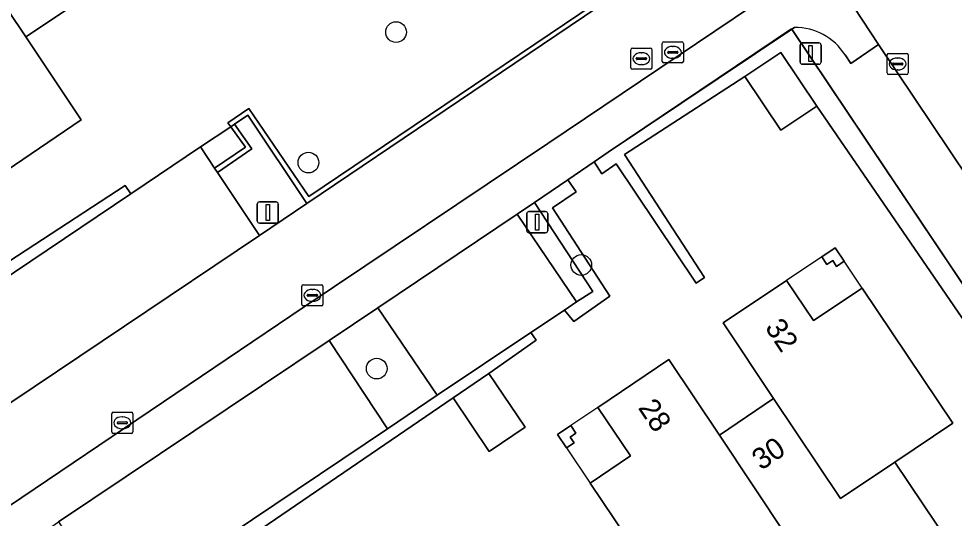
# Model space of a CAD drawing. Extents: x 158793 to 159888, y 384317 to 385256.
# Drawn here: x 159021.67 to 159065.9, y 384757.19 to 384780.77 of the extents above; entities that cross this region are included whole.
import ezdxf

# ---------------------------------------------------------------- set-up
doc = ezdxf.new("R2010")
doc.units = 0
for name, color, linetype in [('IMGEO_Boom', 7, 'Continuous'), ('IMGEO_Erf', 7, 'Continuous'), ('IMGEO_Groenvoorziening', 7, 'Continuous'), ('IMGEO_Haag', 7, 'Continuous'), ('IMGEO_Kolk', 7, 'Continuous'), ('IMGEO_Lichtmast', 7, 'Continuous'), ('IMGEO_Pand', 7, 'Continuous'), ('IMGEO_Pand_nummerreeks', 7, 'Continuous'), ('IMGEO_Pand_overbouw', 7, 'Continuous'), ('IMGEO_Parkeervlak_open', 7, 'Continuous'), ('IMGEO_Rijbaan_lokaal_open', 7, 'Continuous'), ('IMGEO_Rioolput', 7, 'Continuous'), ('IMGEO_Voetpad_open', 7, 'Continuous')]:
    doc.layers.add(name, color=color, linetype=linetype)

msp = doc.modelspace()

# ---------------------------------------------------------------- linework, layer by layer
at = {"layer": 'IMGEO_Boom'}
for centre in [(159039.512, 384780.142), (159035.369, 384773.98), (159048.268, 384769.147), (159038.597, 384764.255)]:
    msp.add_circle(centre, 0.489, dxfattribs=at)
at = {"layer": 'IMGEO_Erf'}
for points in [[(159017.331, 384766.792), (159026.702, 384772.904), (159026.968, 384772.506), (159030.265, 384774.719), (159031.693, 384775.678), (159031.561, 384775.859), (159032.552, 384776.536), (159035.395, 384772.381), (159053.9, 384784.866), (159047.248, 384794.802), (159043.946, 384799.753), (159042.252, 384798.606), (159040.537, 384801.144), (159042.242, 384802.291), (159040.826, 384804.435), (159039.065, 384807.197), (159037.9, 384808.326)], [(159073.463, 384756.185), (159059.406, 384776.641), (159057.7, 384775.506), (159056.001, 384778.049), (159050.315, 384774.368), (159054.088, 384768.56), (159053.696, 384768.284), (159049.917, 384773.924), (159049.246, 384773.456), (159048.88, 384774.02), (159047.625, 384773.167), (159048.029, 384772.609), (159046.909, 384771.846), (159049.623, 384767.68), (159047.913, 384766.485), (159047.469, 384767.022), (159045.889, 384765.966), (159046.137, 384765.595), (159043.901, 384764.02), (159045.607, 384761.491), (159043.913, 384760.348), (159042.209, 384762.873), (159026.999, 384752.507)]]:
    msp.add_lwpolyline(points, dxfattribs=at)
for points in [[(159025.946, 384782.554), (159022.012, 384779.912), (159024.633, 384775.996), (159019.881, 384772.794), (159019.086, 384773.986), (159017.431, 384772.878), (159015.904, 384775.16), (159013.959, 384773.858), (159011.97, 384776.847), (159015.525, 384779.251), (159013.803, 384781.818), (159010.258, 384779.42), (159008.249, 384782.438), (159010.181, 384783.723), (159008.645, 384786.031), (159015.019, 384790.32), (159016.863, 384787.589), (159020.783, 384790.227)], [(159059.638, 384769.531), (159060.27, 384769.954), (159060.694, 384769.323), (159060.336, 384769.083), (159060.152, 384769.357), (159059.877, 384769.173)], [(159052.092, 384752.541), (159052.674, 384752.933), (159048.685, 384758.851), (159050.593, 384760.137), (159049.05, 384762.426), (159052.408, 384764.689), (159054.798, 384761.108), (159057.361, 384762.84), (159054.972, 384766.411), (159057.973, 384768.418), (159059.252, 384766.521), (159061.547, 384768.051), (159065.825, 384761.675), (159063.087, 384759.841), (159065.729, 384755.897), (159058.095, 384750.782), (159058.053, 384750.844), (159054.734, 384748.612)], [(159047.142, 384761.14), (159047.772, 384761.565), (159048.014, 384761.207), (159047.741, 384761.022), (159047.924, 384760.75), (159047.567, 384760.509)]]:
    msp.add_lwpolyline(points, close=True, dxfattribs=at)
at = {"layer": 'IMGEO_Groenvoorziening'}
for points in [[(159037.9, 384808.326), (159039.065, 384807.197), (159040.826, 384804.435), (159042.242, 384802.291), (159043.946, 384799.753), (159047.248, 384794.802), (159053.9, 384784.866), (159035.395, 384772.381), (159032.552, 384776.536), (159031.561, 384775.859), (159031.693, 384775.678), (159031.875, 384775.8), (159032.507, 384776.224), (159035.297, 384772.043), (159052.342, 384783.55)], [(159058.344, 384780.362), (159058.215, 384780.276), (159074.393, 384756.206), (159074.469, 384756.094), (159076.359, 384757.322), (159076.28, 384757.438), (159076.898, 384757.859), (159070.794, 384766.937), (159062.325, 384779.557)], [(159062.325, 384779.557), (159061.017, 384778.659), (159060.74, 384779.07)]]:
    msp.add_lwpolyline(points, dxfattribs=at)
for points in [[(159056.001, 384778.049), (159057.702, 384779.186), (159059.406, 384776.641), (159073.463, 384756.185), (159057.365, 384745.439), (159057.651, 384745), (159058.367, 384745.484), (159074.393, 384756.206), (159058.215, 384780.276), (159049.537, 384774.467), (159048.88, 384774.02), (159049.246, 384773.456), (159049.917, 384773.924), (159053.696, 384768.284), (159054.088, 384768.56), (159050.315, 384774.368)], [(159031.875, 384775.8), (159032.697, 384774.637), (159031.069, 384773.515), (159033.059, 384770.533), (159035.297, 384772.043), (159032.507, 384776.224)], [(159009.089, 384775.491), (159008.609, 384775.168), (159015.56, 384764.829), (159017.507, 384766.155), (159026.968, 384772.506), (159026.702, 384772.904), (159017.331, 384766.792), (159015.636, 384765.657), (159013.986, 384768.23)], [(159046.909, 384771.846), (159048.029, 384772.609), (159047.625, 384773.167), (159046.05, 384772.096), (159048.815, 384767.898), (159048.042, 384767.405), (159047.469, 384767.022), (159047.913, 384766.485), (159049.623, 384767.68)], [(159046.05, 384772.096), (159045.237, 384771.543), (159048.042, 384767.405), (159048.815, 384767.898)], [(159038.657, 384767.131), (159036.344, 384765.586), (159039.107, 384761.407), (159041.461, 384763.006)], [(159042.209, 384762.873), (159043.901, 384764.02), (159046.137, 384765.595), (159045.889, 384765.966), (159041.461, 384763.006), (159039.107, 384761.407), (159026.336, 384752.851), (159024.473, 384751.628), (159030.795, 384742.206), (159031.262, 384742.535), (159027.027, 384748.839), (159025.31, 384751.354), (159026.999, 384752.507)]]:
    msp.add_lwpolyline(points, close=True, dxfattribs=at)
msp.add_arc((159058.37, 384777.542), 2.82, 32.8078, 90.5222, dxfattribs=at)
at = {"layer": 'IMGEO_Haag'}
msp.add_lwpolyline([(159037.9, 384808.326), (159039.065, 384807.197), (159040.826, 384804.435), (159042.242, 384802.291), (159043.946, 384799.753), (159047.248, 384794.802), (159053.9, 384784.866), (159035.395, 384772.381), (159032.552, 384776.536), (159031.561, 384775.859), (159031.693, 384775.678), (159031.875, 384775.8), (159032.507, 384776.224), (159035.297, 384772.043), (159052.342, 384783.55)], dxfattribs=at)
for points in [[(159058.205, 384780.291), (159049.537, 384774.467), (159048.88, 384774.02), (159049.246, 384773.456), (159049.917, 384773.924), (159053.696, 384768.284), (159054.088, 384768.56), (159050.315, 384774.368), (159056.001, 384778.049), (159057.702, 384779.186), (159059.406, 384776.641), (159073.463, 384756.185), (159057.365, 384745.439), (159057.651, 384745), (159058.367, 384745.484), (159074.393, 384756.206)], [(159009.089, 384775.491), (159008.609, 384775.168), (159015.56, 384764.829), (159017.507, 384766.155), (159026.968, 384772.506), (159026.702, 384772.904), (159017.331, 384766.792), (159015.636, 384765.657), (159013.986, 384768.23)], [(159046.909, 384771.846), (159048.029, 384772.609), (159047.625, 384773.167), (159046.05, 384772.096), (159048.815, 384767.898), (159048.042, 384767.405), (159047.469, 384767.022), (159047.913, 384766.485), (159049.623, 384767.68)], [(159026.999, 384752.507), (159042.209, 384762.873), (159043.901, 384764.02), (159046.137, 384765.595), (159045.889, 384765.966), (159041.461, 384763.006), (159039.107, 384761.407), (159026.336, 384752.851), (159024.473, 384751.628), (159030.795, 384742.206), (159031.262, 384742.535), (159027.027, 384748.839), (159025.31, 384751.354)]]:
    msp.add_lwpolyline(points, close=True, dxfattribs=at)
at = {"layer": 'IMGEO_Kolk'}
for p, q in [((159052.095, 384778.76), (159052.095, 384779.612)), ((159052.17, 384779.686), (159053.022, 384779.686)), ((159053.096, 384779.612), (159053.096, 384778.76)), ((159052.354, 384779.18), (159052.354, 384779.192)), ((159052.792, 384779.143), (159052.394, 384779.143)), ((159052.397, 384779.229), (159052.795, 384779.229)), ((159052.583, 384779.466), (159052.608, 384779.466)), ((159052.838, 384779.192), (159052.838, 384779.18)), ((159062.721, 384778.213), (159062.721, 384779.065)), ((159062.796, 384779.139), (159063.648, 384779.139)), ((159063.722, 384779.065), (159063.722, 384778.213)), ((159053.022, 384778.686), (159052.17, 384778.686)), ((159052.606, 384778.906), (159052.581, 384778.906)), ((159062.98, 384778.633), (159062.98, 384778.645)), ((159063.023, 384778.682), (159063.421, 384778.682)), ((159063.209, 384778.919), (159063.234, 384778.919)), ((159063.464, 384778.645), (159063.464, 384778.633)), ((159063.418, 384778.596), (159063.02, 384778.596)), ((159063.232, 384778.359), (159063.207, 384778.359)), ((159063.648, 384778.139), (159062.796, 384778.139)), ((159035.056, 384767.288), (159035.056, 384768.14)), ((159035.131, 384768.214), (159035.983, 384768.214)), ((159036.057, 384768.14), (159036.057, 384767.288)), ((159035.315, 384767.708), (159035.315, 384767.72)), ((159035.753, 384767.671), (159035.355, 384767.671)), ((159035.358, 384767.757), (159035.756, 384767.757)), ((159035.544, 384767.994), (159035.569, 384767.994)), ((159035.799, 384767.72), (159035.799, 384767.708)), ((159035.983, 384767.214), (159035.131, 384767.214)), ((159035.567, 384767.434), (159035.542, 384767.434)), ((159026.071, 384761.27), (159026.071, 384762.122)), ((159026.146, 384762.196), (159026.998, 384762.196)), ((159026.559, 384761.976), (159026.584, 384761.976)), ((159027.072, 384762.122), (159027.072, 384761.27)), ((159026.33, 384761.69), (159026.33, 384761.702)), ((159026.768, 384761.653), (159026.37, 384761.653)), ((159026.373, 384761.739), (159026.771, 384761.739)), ((159026.582, 384761.416), (159026.557, 384761.416)), ((159026.814, 384761.702), (159026.814, 384761.69)), ((159026.998, 384761.196), (159026.146, 384761.196))]:
    msp.add_line(p, q, dxfattribs=at)
for points in [[(159052.095, 384778.76), (159052.095, 384779.612)], [(159052.17, 384779.686), (159053.022, 384779.686)], [(159053.096, 384779.612), (159053.096, 384778.76)], [(159062.721, 384778.213), (159062.721, 384779.065)], [(159062.796, 384779.139), (159063.648, 384779.139)], [(159063.722, 384779.065), (159063.722, 384778.213)], [(159053.022, 384778.686), (159052.17, 384778.686)], [(159063.648, 384778.139), (159062.796, 384778.139)], [(159035.056, 384767.288), (159035.056, 384768.14)], [(159035.131, 384768.214), (159035.983, 384768.214)], [(159036.057, 384768.14), (159036.057, 384767.288)], [(159035.983, 384767.214), (159035.131, 384767.214)], [(159026.071, 384761.27), (159026.071, 384762.122)], [(159026.146, 384762.196), (159026.998, 384762.196)], [(159027.072, 384762.122), (159027.072, 384761.27)], [(159026.998, 384761.196), (159026.146, 384761.196)]]:
    msp.add_lwpolyline(points, dxfattribs=at)
for centre, radius, start, end in [((159052.172, 384779.61), 0.0765, 91.552, 178.448), ((159052.172, 384779.61), 0.0765, 91.552, 178.448), ((159053.02, 384779.61), 0.0765, 1.552, 88.448), ((159053.02, 384779.61), 0.0765, 1.552, 88.448), ((159052.394, 384779.189), 0.0403, 85.8775, 175.7526), ((159052.391, 384779.179), 0.0366, 178.938, 274.7102), ((159052.795, 384779.186), 0.043, 264.8664, 352.4533), ((159052.799, 384779.191), 0.0386, 1.7309, 96.639), ((159062.798, 384779.063), 0.0765, 91.552, 178.448), ((159062.798, 384779.063), 0.0765, 91.552, 178.448), ((159063.646, 384779.063), 0.0765, 1.552, 88.448), ((159063.646, 384779.063), 0.0765, 1.552, 88.448), ((159052.172, 384778.762), 0.0765, 181.552, 268.448), ((159052.172, 384778.762), 0.0765, 181.552, 268.448), ((159053.02, 384778.762), 0.0765, 271.552, 358.448), ((159053.02, 384778.762), 0.0765, 271.552, 358.448), ((159063.02, 384778.642), 0.0403, 85.8775, 175.7526), ((159063.017, 384778.632), 0.0366, 178.938, 274.7102), ((159063.421, 384778.639), 0.043, 264.8664, 352.4533), ((159063.425, 384778.644), 0.0386, 1.7309, 96.639), ((159062.798, 384778.215), 0.0765, 181.552, 268.448), ((159062.798, 384778.215), 0.0765, 181.552, 268.448), ((159063.646, 384778.215), 0.0765, 271.552, 358.448), ((159063.646, 384778.215), 0.0765, 271.552, 358.448), ((159035.133, 384768.138), 0.0765, 91.552, 178.448), ((159035.133, 384768.138), 0.0765, 91.552, 178.448), ((159035.981, 384768.138), 0.0765, 1.552, 88.448), ((159035.981, 384768.138), 0.0765, 1.552, 88.448), ((159035.355, 384767.717), 0.0403, 85.8775, 175.7526), ((159035.352, 384767.707), 0.0366, 178.938, 274.7102), ((159035.756, 384767.714), 0.043, 264.8664, 352.4533), ((159035.76, 384767.719), 0.0386, 1.7309, 96.639), ((159035.133, 384767.29), 0.0765, 181.552, 268.448), ((159035.133, 384767.29), 0.0765, 181.552, 268.448), ((159035.981, 384767.29), 0.0765, 271.552, 358.448), ((159035.981, 384767.29), 0.0765, 271.552, 358.448), ((159026.148, 384762.12), 0.0765, 91.552, 178.448), ((159026.148, 384762.12), 0.0765, 91.552, 178.448), ((159026.996, 384762.12), 0.0765, 1.552, 88.448), ((159026.996, 384762.12), 0.0765, 1.552, 88.448), ((159026.37, 384761.699), 0.0403, 85.8775, 175.7526), ((159026.367, 384761.689), 0.0366, 178.938, 274.7102), ((159026.771, 384761.696), 0.043, 264.8664, 352.4533), ((159026.775, 384761.701), 0.0386, 1.7309, 96.639), ((159026.148, 384761.272), 0.0765, 181.552, 268.448), ((159026.148, 384761.272), 0.0765, 181.552, 268.448), ((159026.996, 384761.272), 0.0765, 271.552, 358.448), ((159026.996, 384761.272), 0.0765, 271.552, 358.448)]:
    msp.add_arc(centre, radius, start, end, dxfattribs=at)
for centre, major_axis, ratio, start_param, end_param in [((159052.582, 384779.186), (-0.387, 0.002), 0.722429, 4.712389, 7.853982), ((159052.607, 384779.186), (-0.39, 0.002), 0.717154, 1.570796, 4.712389), ((159063.208, 384778.639), (-0.387, 0.002), 0.722429, 4.712389, 7.853982), ((159063.233, 384778.639), (-0.39, 0.002), 0.717154, 1.570796, 4.712389), ((159035.543, 384767.714), (-0.387, 0.002), 0.722429, 4.712389, 7.853982), ((159035.568, 384767.714), (-0.39, 0.002), 0.717154, 1.570796, 4.712389), ((159026.558, 384761.696), (-0.387, 0.002), 0.722429, 4.712389, 7.853982), ((159026.583, 384761.696), (-0.39, 0.002), 0.717154, 1.570796, 4.712389)]:
    msp.add_ellipse(centre, major_axis=major_axis, ratio=ratio, start_param=start_param, end_param=end_param, dxfattribs=at)
at = {"layer": 'IMGEO_Lichtmast'}
for p, q in [((159058.61, 384778.729), (159058.61, 384779.529)), ((159058.61, 384779.529), (159058.61, 384778.729)), ((159058.71, 384779.629), (159059.5, 384779.629)), ((159059.5, 384779.629), (159058.71, 384779.629)), ((159059.6, 384779.529), (159059.6, 384778.729)), ((159059.6, 384778.729), (159059.6, 384779.529)), ((159059.5, 384778.629), (159058.71, 384778.629)), ((159058.71, 384778.629), (159059.5, 384778.629)), ((159032.953, 384771.224), (159032.953, 384772.024)), ((159032.953, 384772.024), (159032.953, 384771.224)), ((159033.053, 384772.124), (159033.843, 384772.124)), ((159033.843, 384772.124), (159033.053, 384772.124)), ((159033.943, 384772.024), (159033.943, 384771.224)), ((159033.943, 384771.224), (159033.943, 384772.024)), ((159045.689, 384770.772), (159045.689, 384771.572)), ((159045.689, 384771.572), (159045.689, 384770.772)), ((159045.789, 384771.672), (159046.579, 384771.672)), ((159046.579, 384771.672), (159045.789, 384771.672)), ((159046.679, 384771.572), (159046.679, 384770.772)), ((159046.679, 384770.772), (159046.679, 384771.572)), ((159033.843, 384771.124), (159033.053, 384771.124)), ((159033.053, 384771.124), (159033.843, 384771.124)), ((159046.579, 384770.672), (159045.789, 384770.672)), ((159045.789, 384770.672), (159046.579, 384770.672))]:
    msp.add_line(p, q, dxfattribs=at)
for points in [[(159059.03, 384779.504), (159059.18, 384779.504), (159059.18, 384778.754), (159059.03, 384778.754), (159059.03, 384779.504)], [(159033.373, 384771.999), (159033.523, 384771.999), (159033.523, 384771.249), (159033.373, 384771.249), (159033.373, 384771.999)], [(159046.109, 384771.547), (159046.259, 384771.547), (159046.259, 384770.797), (159046.109, 384770.797), (159046.109, 384771.547)]]:
    msp.add_lwpolyline(points, dxfattribs=at)
for centre, start, end in [((159058.71, 384779.529), 90, 180), ((159058.71, 384779.529), 90, 180), ((159059.5, 384779.529), 0, 90), ((159059.5, 384779.529), 360, 90), ((159058.71, 384778.729), 180, 270), ((159058.71, 384778.729), 180, 270), ((159059.5, 384778.729), 270, 0), ((159059.5, 384778.729), 270, 0), ((159033.053, 384772.024), 90, 180), ((159033.053, 384772.024), 90, 180), ((159033.843, 384772.024), 0, 90), ((159033.843, 384772.024), 360, 90), ((159045.789, 384771.572), 90, 180), ((159045.789, 384771.572), 90, 180), ((159046.579, 384771.572), 0, 90), ((159046.579, 384771.572), 360, 90), ((159033.053, 384771.224), 180, 270), ((159033.053, 384771.224), 180, 270), ((159033.843, 384771.224), 270, 0), ((159033.843, 384771.224), 270, 0), ((159045.789, 384770.772), 180, 270), ((159045.789, 384770.772), 180, 270), ((159046.579, 384770.772), 270, 0), ((159046.579, 384770.772), 270, 0)]:
    msp.add_arc(centre, 0.1, start, end, dxfattribs=at)
at = {"layer": 'IMGEO_Pand'}
for points in [[(159020.783, 384790.227), (159016.863, 384787.589), (159018.578, 384785.048), (159013.803, 384781.818), (159015.525, 384779.251), (159020.295, 384782.477), (159022.012, 384779.912), (159025.946, 384782.554)], [(159022.012, 384779.912), (159020.295, 384782.477), (159015.525, 384779.251), (159011.97, 384776.847), (159013.959, 384773.858), (159015.904, 384775.16), (159017.431, 384772.878), (159019.086, 384773.986), (159019.881, 384772.794), (159024.633, 384775.996)], [(159056.001, 384778.049), (159057.7, 384775.506), (159059.406, 384776.641), (159057.702, 384779.186)], [(159059.638, 384769.531), (159059.877, 384769.173), (159060.152, 384769.357), (159060.336, 384769.083), (159060.694, 384769.323), (159060.27, 384769.954)], [(159061.547, 384768.051), (159059.252, 384766.521), (159057.973, 384768.418), (159054.972, 384766.411), (159057.361, 384762.84), (159060.518, 384758.12), (159063.087, 384759.841), (159065.825, 384761.675)], [(159054.798, 384761.108), (159052.408, 384764.689), (159049.05, 384762.426), (159050.593, 384760.137), (159048.685, 384758.851), (159052.674, 384752.933), (159052.721, 384752.863), (159055.458, 384754.703), (159057.953, 384756.38)], [(159043.901, 384764.02), (159042.209, 384762.873), (159043.913, 384760.348), (159045.607, 384761.491)], [(159063.087, 384759.841), (159060.518, 384758.12), (159057.361, 384762.84), (159054.798, 384761.108), (159057.953, 384756.38), (159055.458, 384754.703), (159052.721, 384752.863), (159052.674, 384752.933), (159052.092, 384752.541), (159054.734, 384748.612), (159058.053, 384750.844), (159058.095, 384750.782), (159065.729, 384755.897)], [(159048.014, 384761.207), (159047.772, 384761.565), (159047.142, 384761.14), (159047.567, 384760.509), (159047.924, 384760.75), (159047.741, 384761.022)]]:
    msp.add_lwpolyline(points, close=True, dxfattribs=at)
at = {"layer": 'IMGEO_Pand_overbouw'}
for points in [[(159059.638, 384769.531), (159057.973, 384768.418), (159059.252, 384766.521), (159061.547, 384768.051), (159060.694, 384769.323), (159060.27, 384769.954)], [(159047.567, 384760.509), (159048.685, 384758.851), (159050.593, 384760.137), (159049.05, 384762.426), (159047.772, 384761.565), (159047.142, 384761.14)]]:
    msp.add_lwpolyline(points, close=True, dxfattribs=at)
at = {"layer": 'IMGEO_Parkeervlak_open'}
for points in [[(159033.059, 384770.533), (159031.069, 384773.515), (159030.934, 384773.717), (159030.265, 384774.719), (159026.968, 384772.506), (159017.507, 384766.155), (159020.274, 384761.982)], [(159048.042, 384767.405), (159045.237, 384771.543), (159038.657, 384767.131), (159041.461, 384763.006), (159045.889, 384765.966), (159047.469, 384767.022)], [(159036.344, 384765.586), (159023.56, 384757.022), (159026.336, 384752.851), (159039.107, 384761.407)]]:
    msp.add_lwpolyline(points, close=True, dxfattribs=at)
at = {"layer": 'IMGEO_Rijbaan_lokaal_open'}
for points in [[(159020.585, 384757.356), (159035.163, 384767.176), (159046.693, 384774.887), (159056.355, 384781.391), (159054.061, 384784.728), (159052.342, 384783.55), (159035.297, 384772.043), (159033.059, 384770.533), (159020.274, 384761.982)], [(159061.174, 384781.31), (159062.325, 384779.557), (159070.794, 384766.937), (159076.898, 384757.859), (159079.959, 384753.282), (159080.521, 384752.446), (159084.986, 384745.797), (159085.468, 384745.079), (159093.015, 384733.846), (159096.938, 384728.011), (159100.183, 384723.227)]]:
    msp.add_lwpolyline(points, dxfattribs=at)
at = {"layer": 'IMGEO_Rioolput'}
for p, q in [((159050.609, 384778.461), (159050.609, 384779.313)), ((159050.684, 384779.387), (159051.536, 384779.387)), ((159051.097, 384779.167), (159051.122, 384779.167)), ((159051.61, 384779.313), (159051.61, 384778.461)), ((159050.868, 384778.881), (159050.868, 384778.893)), ((159051.306, 384778.844), (159050.908, 384778.844)), ((159050.911, 384778.93), (159051.309, 384778.93)), ((159051.352, 384778.893), (159051.352, 384778.881)), ((159051.536, 384778.387), (159050.684, 384778.387)), ((159051.12, 384778.607), (159051.095, 384778.607))]:
    msp.add_line(p, q, dxfattribs=at)
for points in [[(159050.609, 384778.461), (159050.609, 384779.313)], [(159050.684, 384779.387), (159051.536, 384779.387)], [(159051.61, 384779.313), (159051.61, 384778.461)], [(159051.536, 384778.387), (159050.684, 384778.387)]]:
    msp.add_lwpolyline(points, dxfattribs=at)
for centre, radius, start, end in [((159050.686, 384779.311), 0.0765, 91.552, 178.448), ((159050.686, 384779.311), 0.0765, 91.552, 178.448), ((159051.534, 384779.311), 0.0765, 1.552, 88.448), ((159051.534, 384779.311), 0.0765, 1.552, 88.448), ((159050.908, 384778.89), 0.0403, 85.8775, 175.7526), ((159050.905, 384778.88), 0.0366, 178.938, 274.7102), ((159051.309, 384778.887), 0.043, 264.8664, 352.4533), ((159051.313, 384778.892), 0.0386, 1.7309, 96.639), ((159050.686, 384778.463), 0.0765, 181.552, 268.448), ((159050.686, 384778.463), 0.0765, 181.552, 268.448), ((159051.534, 384778.463), 0.0765, 271.552, 358.448), ((159051.534, 384778.463), 0.0765, 271.552, 358.448)]:
    msp.add_arc(centre, radius, start, end, dxfattribs=at)
for centre, major_axis, ratio, start_param, end_param in [((159051.096, 384778.887), (-0.387, 0.002), 0.722429, 4.712389, 7.853982), ((159051.121, 384778.887), (-0.39, 0.002), 0.717154, 1.570796, 4.712389)]:
    msp.add_ellipse(centre, major_axis=major_axis, ratio=ratio, start_param=start_param, end_param=end_param, dxfattribs=at)
at = {"layer": 'IMGEO_Voetpad_open'}
for points in [[(159057.22, 384781.983), (159056.355, 384781.391), (159046.693, 384774.887), (159035.163, 384767.176), (159020.585, 384757.356), (159021.692, 384755.75), (159022.554, 384756.332), (159023.56, 384757.022), (159036.344, 384765.586), (159038.657, 384767.131), (159045.237, 384771.543)], [(159060.74, 384779.07), (159061.017, 384778.659), (159062.325, 384779.557), (159061.174, 384781.31)], [(159045.237, 384771.543), (159046.05, 384772.096), (159047.625, 384773.167), (159048.88, 384774.02), (159049.537, 384774.467), (159058.215, 384780.276), (159058.344, 384780.362)]]:
    msp.add_lwpolyline(points, dxfattribs=at)
for points in [[(159031.693, 384775.678), (159030.265, 384774.719), (159030.934, 384773.717), (159032.398, 384774.707)], [(159031.875, 384775.8), (159031.693, 384775.678), (159032.398, 384774.707), (159030.934, 384773.717), (159031.069, 384773.515), (159032.697, 384774.637)]]:
    msp.add_lwpolyline(points, close=True, dxfattribs=at)
msp.add_arc((159058.37, 384777.542), 2.82, 32.8078, 90.5222, dxfattribs=at)

# ---------------------------------------------------------------- texts
at = {"layer": 'IMGEO_Pand_nummerreeks'}
for s, rotation, p in [('32', 303.7814, (159056.923, 384766.193)), ('28', 303.7184, (159050.927, 384762.406)), ('30', 34.0509, (159056.772, 384759.424))]:
    msp.add_text(s, height=1, rotation=rotation, dxfattribs=at).set_placement(p)

doc.saveas('drawing.dxf')
